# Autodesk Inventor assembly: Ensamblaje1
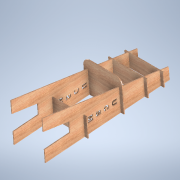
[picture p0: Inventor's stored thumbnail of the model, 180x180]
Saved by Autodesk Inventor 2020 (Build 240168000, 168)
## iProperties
Created: 2020-03
Part Number: Ensamblaje1
Document SubType Name: Assembly
Designer: Arias
Author: Arias
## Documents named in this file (7)
- C:\Users\Arias\Desktop\DISEÑOS\TAREA 8\Ensamblaje1.iam
- C:\Users\Arias\Desktop\DISEÑOS\TAREA 8\TERCERA REPISA.ipt
- C:\Users\Arias\Desktop\DISEÑOS\TAREA 8\LATERAL IZQUIERDA.ipt
- C:\Users\Arias\Desktop\DISEÑOS\TAREA 8\PRIMERA REPISA.ipt
- C:\Users\Arias\Desktop\DISEÑOS\TAREA 8\SEGUNDA REPISA.ipt
- C:\Users\Arias\Desktop\DISEÑOS\TAREA 8\LATERAL DERECHA.ipt
- C:\Users\Arias\Desktop\DISEÑOS\TAREA 8\POSAPIES.ipt
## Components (6 placed, 6 different names)
1. TERCERA REPISA:1 — Coincidencia:1, Coincidencia:2, Coincidencia:3, Coincidencia:8
2. LATERAL IZQUIERDA:1 — Coincidencia:1, Coincidencia:2, Coincidencia:3, Nivelación:1, Nivelación:2, Coincidencia:4, Coincidencia:5, Coincidencia:6, Coincidencia:7, Coincidencia:9, Coincidencia:10, Coincidencia:14
3. PRIMERA REPISA:1 — Coincidencia:5, Coincidencia:7, Coincidencia:10
4. SEGUNDA REPISA:1 — Coincidencia:4, Coincidencia:6, Coincidencia:9
5. LATERAL DERECHA:1 — Nivelación:1, Nivelación:2, Coincidencia:8, Coincidencia:11, Coincidencia:12, Coincidencia:13
6. POSAPIES:1 — Coincidencia:11, Coincidencia:12, Coincidencia:13
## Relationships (16: Mate 14, Flush 2)
- Coincidencia:1 [Mate]: TERCERA REPISA:1 ↔ LATERAL IZQUIERDA:1
- Coincidencia:2 [Mate]: TERCERA REPISA:1 ↔ LATERAL IZQUIERDA:1
- Coincidencia:3 [Mate]: TERCERA REPISA:1 ↔ LATERAL IZQUIERDA:1
- Nivelación:1 [Flush]: LATERAL IZQUIERDA:1 ↔ LATERAL DERECHA:1
- Nivelación:2 [Flush]: LATERAL IZQUIERDA:1 ↔ LATERAL DERECHA:1
- Coincidencia:4 [Mate]: LATERAL IZQUIERDA:1 ↔ SEGUNDA REPISA:1
- Coincidencia:5 [Mate]: LATERAL IZQUIERDA:1 ↔ PRIMERA REPISA:1
- Coincidencia:6 [Mate]: LATERAL IZQUIERDA:1 ↔ SEGUNDA REPISA:1
- Coincidencia:7 [Mate]: LATERAL IZQUIERDA:1 ↔ PRIMERA REPISA:1
- Coincidencia:8 [Mate]: TERCERA REPISA:1 ↔ LATERAL DERECHA:1
- Coincidencia:9 [Mate]: LATERAL IZQUIERDA:1 ↔ SEGUNDA REPISA:1
- Coincidencia:10 [Mate]: LATERAL IZQUIERDA:1 ↔ PRIMERA REPISA:1
- Coincidencia:11 [Mate]: LATERAL DERECHA:1 ↔ POSAPIES:1
- Coincidencia:12 [Mate]: LATERAL DERECHA:1 ↔ POSAPIES:1
- Coincidencia:13 [Mate]: LATERAL DERECHA:1 ↔ POSAPIES:1
- Coincidencia:14 [Mate]: LATERAL IZQUIERDA:1
